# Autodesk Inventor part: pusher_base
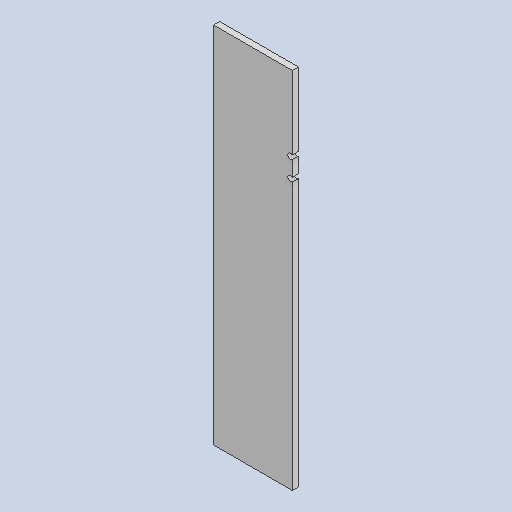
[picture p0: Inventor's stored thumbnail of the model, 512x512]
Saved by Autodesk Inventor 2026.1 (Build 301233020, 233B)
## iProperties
Created: 2026-10
Part Number: pusher_base
Material: Generic
Document SubType Name: Modeling
Designer: alolo
Density: 1 g/cm^3
Appearance: Default
Author: alolo
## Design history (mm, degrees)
sketch "Sketch1"
  geometry: L1 (0, 0)-(65, 0); L2 (65, 0)-(65, 300); L3 (65, 300)-(0, 300); L4 (0, 300)-(0, 0); L5 (0, 0)-(65, 0); L6 (65, 0)-(65, -300); L7 (65, -300)-(0, -300); L8 (0, -300)-(0, 0)
  constraints: 16 end point, 4 parallel, 2 horizontal, 2 perpendicular
  dimensions: "d0" = 65 distance of L3.end L2.end (= slide_width); "d1" = 300 distance of L2.end L1.end; "d4" = 300 distance of L5.end L6.end; "d5" = 65 distance of L6.end L7.end (= d0)
extrude "Extrusion1" new body sketch "Sketch1" distance "d2" = 5 (= wood_thickness); taper "d3" = 0 deg
sketch "Sketch2"
  geometry: 2 further points
hole "Hole1" sketch "Sketch2" at (63.5, 222), (63.5, 238) diameter "d6" = 4.5; stored, may be unused: countersink angle "d10" = 90 deg, drill point angle "d12" = 0 deg; dims "d7" = 6, "d8" = 4, "d9" = 2, "d11" = 8
body "Solid1"
other parameters: "slide_length" = 195 [user parameter], "slide_angle" = 7 deg [user parameter], "slide_width" = 65 [user parameter; used in 1 equation term], "wood_thickness" = 5 [user parameter; used in 1 equation term], "aclyric_thickness" = 6 [user parameter]
